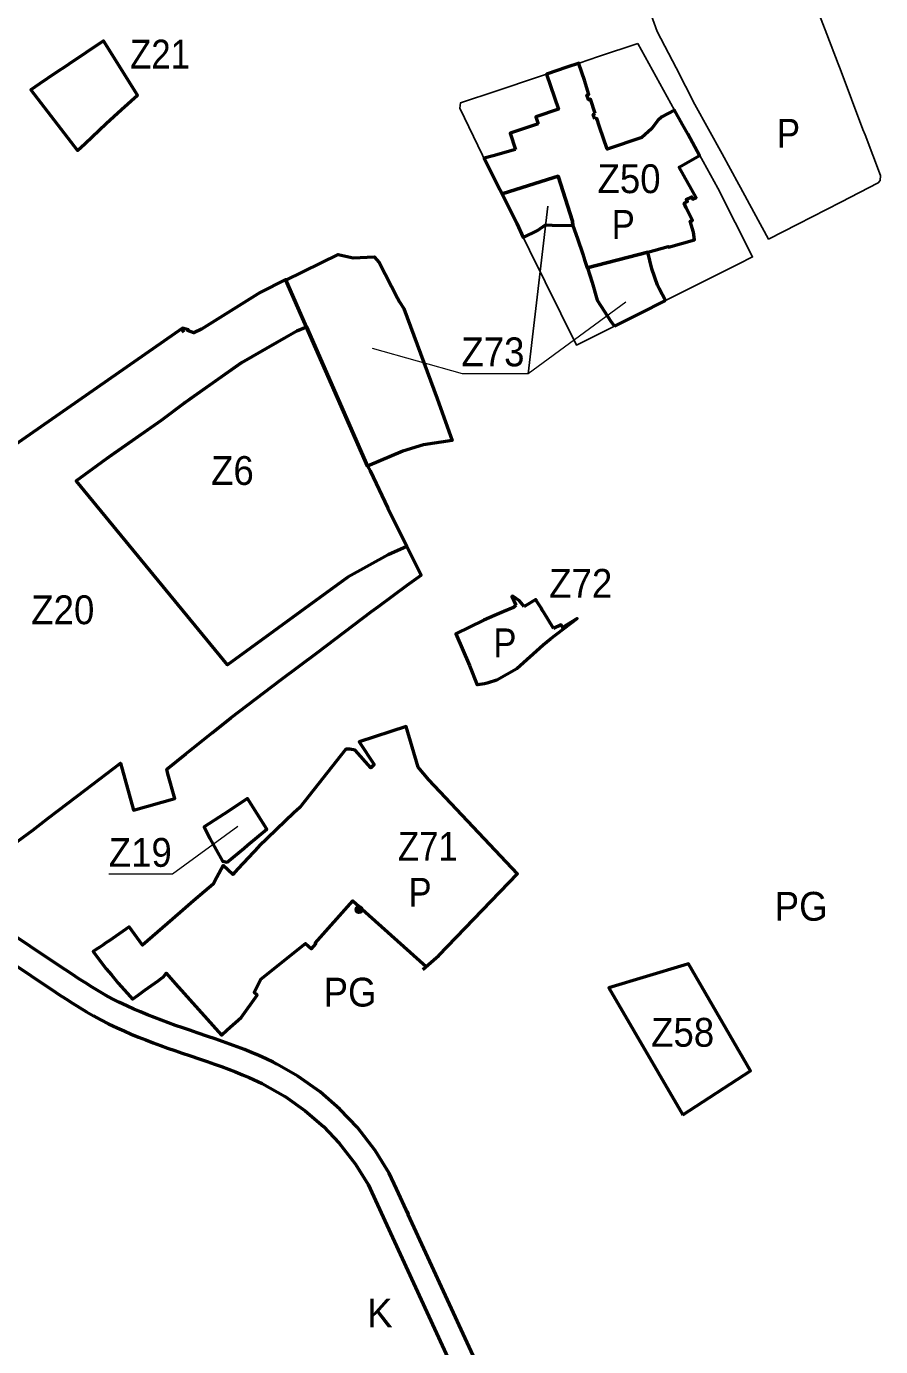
# Model space of a CAD drawing. Extents: x -650246 to -642674, y -1074280 to -1066767.
# Drawn here: x -648043 to -647332, y -1071788 to -1070690 of the extents above; entities that cross this region are included whole.
import ezdxf

# ---------------------------------------------------------------- set-up
doc = ezdxf.new("R2010")
doc.units = 0
doc.header["$LTSCALE"] = 9.6
doc.header["$PDMODE"] = 32
doc.header["$PDSIZE"] = 4.8
for name, color, linetype, lineweight in [('42', 7, 'Continuous', 25), ('44', 7, 'Continuous', 53), ('45', 7, 'Continuous', 53), ('46', 7, 'Continuous', 13), ('48', 7, 'Continuous', 13), ('60', 7, 'Continuous', 35)]:
    doc.layers.add(name, color=color, linetype=linetype, lineweight=lineweight)

msp = doc.modelspace()

# ---------------------------------------------------------------- linework, layer by layer
at = {"layer": '42'}
for points in [[(-647523.27, -1070680.11), (-647518.19, -1070693.93), (-647502.59, -1070724.13), (-647486.84, -1070754.54), (-647464.3, -1070795.6), (-647450.23, -1070821.25), (-647448.84, -1070823.79), (-647437.79, -1070844.12), (-647425.58, -1070866.7), (-647401.15, -1070854.25), (-647365.48, -1070835.85), (-647334.27, -1070819.86), (-647332.51, -1070817.97), (-647332.25, -1070813.72), (-647345.18, -1070779.89), (-647346.96, -1070775.41), (-647365.94, -1070725.08), (-647367.67, -1070720.73), (-647377.04, -1070696.22), (-647386.39, -1070671.74)], [(-647717.363, -1071306.29), (-647727.368, -1071272.362), (-647766.35, -1071285.11), (-647753.89, -1071303.94), (-647756.67, -1071306.77), (-647769.85, -1071291.91), (-647774.14, -1071291.34), (-647777.4, -1071291.32), (-647815.95, -1071339.71), (-647820.93, -1071344.25), (-647849.86, -1071372.18), (-647867.45, -1071390.95), (-647871.68, -1071395.59), (-647879.76, -1071387.96), (-647885.05, -1071397.88), (-647888.11, -1071403.61), (-647895.29, -1071409.81), (-647904.3, -1071417.58), (-647911.04, -1071423.39), (-647913.31, -1071425.35), (-647921.96, -1071432.81), (-647946.78, -1071454.23), (-647957.906, -1071439.06), (-647974.66, -1071450.62), (-647977.28, -1071452.43), (-647979.88, -1071454.22), (-647982.46, -1071456), (-647985.06, -1071457.79), (-647987.8, -1071459.68), (-647984, -1071465), (-647977.13, -1071474.05), (-647972.76, -1071479)], [(-647710.546, -1071472.023), (-647700.078, -1071462.96), (-647634.524, -1071394.901), (-647708.429, -1071316.821), (-647717.363, -1071306.29)], [(-647803.1, -1071452.66), (-647771.82, -1071417.42), (-647710.546, -1071472.023)], [(-647848.4, -1071482.78), (-647810.97, -1071452.92), (-647806.15, -1071457.48)], [(-647806.15, -1071457.48), (-647802.53, -1071453.19), (-647803.1, -1071452.66)], [(-647972.76, -1071479), (-647967.13, -1071486.01), (-647957.07, -1071497.13), (-647955.14, -1071499.23), (-647950.56, -1071495.85), (-647944.81, -1071491.78), (-647939.31, -1071487.88), (-647933.88, -1071484.04), (-647931.17, -1071482.12), (-647929.26, -1071480.77), (-647927.2, -1071477.54), (-647919.22, -1071486.5), (-647881.16, -1071529.25)], [(-647881.16, -1071529.25), (-647876.27, -1071524.96), (-647864.69, -1071514.65), (-647851.45, -1071495.96), (-647853.77, -1071493.78), (-647848.4, -1071482.78)]]:
    msp.add_lwpolyline(points, dxfattribs=at)
msp.add_lwpolyline([(-647534.33, -1070703.84), (-647567.08, -1070714.8), (-647583.22, -1070720.2), (-647651.82, -1070743.17), (-647682.08, -1070753.29), (-647682.67, -1070757.67), (-647663.71, -1070796.77), (-647585.55, -1070954.94), (-647553.94, -1070939.11), (-647532.58, -1070928.392), (-647511.37, -1070917.79), (-647501.26, -1070912.72), (-647450.8, -1070887.42), (-647438.82, -1070881.43), (-647467.89, -1070824.15), (-647480.13, -1070802.09), (-647503.76, -1070759.31)], close=True, dxfattribs=at)
at = {"layer": '44'}
for points in [[(-647834.953, -1071553.406), (-647837.929, -1071551.872), (-647843.891, -1071549), (-647849.898, -1071546.282), (-647855.937, -1071543.707), (-647861.998, -1071541.254), (-647868.073, -1071538.911), (-647874.155, -1071536.658), (-647880.233, -1071534.48), (-647886.305, -1071532.36), (-647892.363, -1071530.282), (-647901.28, -1071527.249), (-647907.294, -1071525.204), (-647913.282, -1071523.152), (-647919.238, -1071521.081), (-647925.157, -1071518.976), (-647931.035, -1071516.824), (-647936.866, -1071514.613), (-647942.644, -1071512.329), (-647948.363, -1071509.96), (-647954.016, -1071507.496), (-647959.792, -1071504.833), (-647966.547, -1071501.883), (-647972.035, -1071499.009), (-647977.67, -1071495.885), (-647983.266, -1071492.628), (-647988.829, -1071489.259), (-647994.366, -1071485.79), (-647999.887, -1071482.241), (-648005.399, -1071478.627), (-648010.917, -1071474.963), (-648016.446, -1071471.268), (-648063.593, -1071439.723)], [(-648074.86, -1071456.248), (-648027.562, -1071487.894), (-648022.005, -1071491.607), (-648016.415, -1071495.321), (-648010.777, -1071499.017), (-648005.082, -1071502.678), (-647999.319, -1071506.287), (-647993.478, -1071509.826), (-647987.55, -1071513.275), (-647981.525, -1071516.615), (-647975.201, -1071519.929), (-647967.982, -1071523.081), (-647962.2, -1071525.746), (-647956.187, -1071528.368), (-647950.146, -1071530.869), (-647944.088, -1071533.263), (-647938.019, -1071535.566), (-647931.945, -1071537.788), (-647925.874, -1071539.949), (-647919.808, -1071542.058), (-647913.756, -1071544.132), (-647907.72, -1071546.185), (-647898.827, -1071549.208), (-647892.847, -1071551.26), (-647886.903, -1071553.336), (-647881.001, -1071555.45), (-647875.147, -1071557.619), (-647869.348, -1071559.856), (-647863.611, -1071562.177), (-647857.944, -1071564.594), (-647847.103, -1071569.497)], [(-647725.629, -1071678.373), (-647735.352, -1071657.117), (-647741.34, -1071644.028), (-647753.065, -1071625.201), (-647767.784, -1071606.225), (-647782.408, -1071590.847), (-647798.911, -1071576.526), (-647817.375, -1071563.458), (-647834.953, -1071553.406)], [(-647847.103, -1071569.497), (-647828.141, -1071580.34), (-647811.272, -1071592.28), (-647796.24, -1071605.324), (-647782.97, -1071619.278)], [(-647782.97, -1071619.278), (-647769.498, -1071636.647), (-647758.994, -1071653.513), (-647743.48, -1071687.426), (-647611.514, -1071974.086)], [(-647563.77, -1071994.38), (-647564.751, -1071987.939), (-647566.62, -1071981.3), (-647569.422, -1071974.943), (-647573.283, -1071969.627), (-647575.415, -1071967.709), (-647577.881, -1071965.979), (-647581.036, -1071964.346), (-647584.363, -1071963.196), (-647588.064, -1071962.51), (-647591.518, -1071962.387), (-647594.731, -1071962.714), (-647725.614, -1071678.405), (-647726.774, -1071675.885), (-647725.629, -1071678.373)]]:
    msp.add_lwpolyline(points, dxfattribs=at)
at = {"layer": '45'}
for p, q in [((-647914.73, -1070941.682), (-647912.347, -1070944.065)), ((-647914.73, -1070941.682), (-647912.347, -1070944.065)), ((-647713.442, -1071474.53), (-647700.078, -1071462.96)), ((-647713.442, -1071474.53), (-647700.078, -1071462.96))]:
    msp.add_line(p, q, dxfattribs=at)
for points in [[(-648032.601, -1070737.472), (-648039.82, -1070742.33), (-648000.85, -1070792.88), (-647994.63, -1070787.05), (-647982.89, -1070776.05), (-647976.97, -1070770.51), (-647964.21, -1070758.77), (-647951.11, -1070746.78), (-647979.17, -1070701.65), (-648008.28, -1070720.96), (-648009.29, -1070721.79), (-648019.49, -1070728.65)], [(-647827.363, -1070900.725), (-647783.95, -1070879.58), (-647771.47, -1070882.27), (-647753.81, -1070881.3), (-647749.75, -1070886.1), (-647734.48, -1070915.94), (-647732.97, -1070918.87), (-647729.27, -1070924.35), (-647701.45, -1070999.4), (-647688.9, -1071034.18), (-647712.74, -1071037.99), (-647730.17, -1071043.21), (-647759.52, -1071055.67)], [(-647827.363, -1070900.725), (-647783.95, -1070879.58), (-647771.47, -1070882.27), (-647753.81, -1070881.3), (-647749.75, -1070886.1), (-647734.48, -1070915.94), (-647732.97, -1070918.87), (-647729.27, -1070924.35), (-647701.45, -1070999.4), (-647688.9, -1071034.18), (-647712.74, -1071037.99), (-647730.17, -1071043.21), (-647759.52, -1071055.67)], [(-648001.766, -1071068.02), (-648001.922, -1071067.83), (-647973.304, -1071046.814), (-647930.96, -1071017.383), (-647912.11, -1071003.11), (-647906.9, -1070999.39), (-647875.248, -1070977.173), (-647864.03, -1070969.3), (-647843.928, -1070957.692), (-647818.33, -1070942.91), (-647810.243, -1070939.825), (-647759.52, -1071055.67), (-647757.19, -1071059.66), (-647742.64, -1071090.72), (-647726.74, -1071122.48), (-647742.35, -1071129.43), (-647775.982, -1071148.001), (-647775.982, -1071148.001), (-647875.939, -1071221.104)], [(-647974.66, -1071450.62), (-647977.28, -1071452.43), (-647979.88, -1071454.22), (-647982.46, -1071456), (-647985.06, -1071457.79), (-647987.8, -1071459.68), (-647984, -1071465), (-647977.13, -1071474.05), (-647972.76, -1071479), (-647967.13, -1071486.01), (-647957.07, -1071497.13), (-647955.14, -1071499.23), (-647950.56, -1071495.85), (-647944.81, -1071491.78), (-647939.31, -1071487.88), (-647933.88, -1071484.04), (-647931.17, -1071482.12), (-647929.26, -1071480.77), (-647927.2, -1071477.54), (-647919.22, -1071486.5), (-647881.16, -1071529.25), (-647876.27, -1071524.96), (-647864.69, -1071514.65), (-647851.45, -1071495.96), (-647853.77, -1071493.78), (-647848.4, -1071482.78), (-647810.97, -1071452.92), (-647806.15, -1071457.48), (-647802.53, -1071453.19), (-647803.1, -1071452.66), (-647771.82, -1071417.42), (-647710.546, -1071472.023), (-647700.078, -1071462.96), (-647634.524, -1071394.901), (-647708.429, -1071316.821), (-647717.363, -1071306.29), (-647727.368, -1071272.362), (-647766.35, -1071285.11), (-647753.89, -1071303.94), (-647756.67, -1071306.77), (-647769.85, -1071291.91), (-647774.14, -1071291.34), (-647777.4, -1071291.32), (-647815.95, -1071339.71), (-647820.93, -1071344.25), (-647849.86, -1071372.18), (-647867.45, -1071390.95), (-647871.68, -1071395.59), (-647879.76, -1071387.96), (-647885.05, -1071397.88), (-647888.11, -1071403.61), (-647895.29, -1071409.81), (-647904.3, -1071417.58), (-647911.04, -1071423.39), (-647913.31, -1071425.35), (-647921.96, -1071432.81), (-647946.78, -1071454.23), (-647957.906, -1071439.06)], [(-647974.66, -1071450.62), (-647977.28, -1071452.43), (-647979.88, -1071454.22), (-647982.46, -1071456), (-647985.06, -1071457.79), (-647987.8, -1071459.68), (-647984, -1071465), (-647977.13, -1071474.05), (-647972.76, -1071479), (-647967.13, -1071486.01), (-647957.07, -1071497.13), (-647955.14, -1071499.23), (-647950.56, -1071495.85), (-647944.81, -1071491.78), (-647939.31, -1071487.88), (-647933.88, -1071484.04), (-647931.17, -1071482.12), (-647929.26, -1071480.77), (-647927.2, -1071477.54), (-647919.22, -1071486.5), (-647881.16, -1071529.25), (-647876.27, -1071524.96), (-647864.69, -1071514.65), (-647851.45, -1071495.96), (-647853.77, -1071493.78), (-647848.4, -1071482.78), (-647810.97, -1071452.92), (-647806.15, -1071457.48), (-647802.53, -1071453.19), (-647803.1, -1071452.66), (-647771.82, -1071417.42), (-647710.546, -1071472.023), (-647700.078, -1071462.96), (-647634.524, -1071394.901), (-647708.429, -1071316.821), (-647717.363, -1071306.29), (-647727.368, -1071272.362), (-647766.35, -1071285.11), (-647753.89, -1071303.94), (-647756.67, -1071306.77), (-647769.85, -1071291.91), (-647774.14, -1071291.34), (-647777.4, -1071291.32), (-647815.95, -1071339.71), (-647820.93, -1071344.25), (-647849.86, -1071372.18), (-647867.45, -1071390.95), (-647871.68, -1071395.59), (-647879.76, -1071387.96), (-647885.05, -1071397.88), (-647888.11, -1071403.61), (-647895.29, -1071409.81), (-647904.3, -1071417.58), (-647911.04, -1071423.39), (-647913.31, -1071425.35), (-647921.96, -1071432.81), (-647946.78, -1071454.23), (-647957.906, -1071439.06)], [(-647879.09, -1071345.3), (-647895.37, -1071355.96), (-647890.7, -1071365.52), (-647880.14, -1071384.32), (-647876.34, -1071385.2), (-647862.25, -1071373.55), (-647859.44, -1071371.23), (-647843.23, -1071357.82), (-647859.31, -1071332.34)], [(-647879.09, -1071345.3), (-647895.37, -1071355.96), (-647890.7, -1071365.52), (-647880.14, -1071384.32), (-647876.34, -1071385.2), (-647862.25, -1071373.55), (-647859.44, -1071371.23), (-647843.23, -1071357.82), (-647859.31, -1071332.34)], [(-647497.04, -1071595.66), (-647440.67, -1071558.93), (-647492.3, -1071470), (-647495.85, -1071471.06), (-647558.654, -1071489.738)], [(-647497.04, -1071595.66), (-647440.67, -1071558.93), (-647492.3, -1071470), (-647495.85, -1071471.06), (-647558.654, -1071489.738)]]:
    msp.add_lwpolyline(points, close=True, dxfattribs=at)
for points in [[(-647569.92, -1070762.24), (-647573.88, -1070750.25), (-647575.58, -1070750.83), (-647576.81, -1070746.86), (-647575.09, -1070746.33), (-647578.79, -1070734.33), (-647583.38, -1070720.9), (-647583.22, -1070720.2), (-647593.6, -1070723.68), (-647610.33, -1070729.28), (-647600.53, -1070758.65), (-647619.2, -1070764.85), (-647617.36, -1070770.69)], [(-647636.12, -1070792.13), (-647654.89, -1070797.23), (-647662.26, -1070799.23), (-647650.908, -1070822.34), (-647647.405, -1070829.08), (-647609.58, -1070817.06), (-647600.8, -1070814.27), (-647588.89, -1070851.67), (-647588.4, -1070855.25), (-647584.6, -1070866.3), (-647580.22, -1070879.3), (-647578.703, -1070883.851), (-647578.703, -1070883.851), (-647576.469, -1070890.564), (-647526.13, -1070877.41), (-647509.1, -1070872.96), (-647508.96, -1070873.41), (-647487.16, -1070867.32), (-647487.91, -1070860.91), (-647490.92, -1070851.82), (-647488.8, -1070851.12), (-647494.1, -1070840.58), (-647495.93, -1070836.86), (-647493.16, -1070835.5), (-647494.03, -1070833.64), (-647489.55, -1070831.53), (-647488.75, -1070833.37), (-647485.9, -1070832), (-647500.07, -1070806.87), (-647500.07, -1070806.87), (-647483.16, -1070797.07), (-647492.81, -1070779.18), (-647492.81, -1070779.18), (-647497.227, -1070771.165), (-647503.76, -1070759.31), (-647514.49, -1070764.93), (-647517.61, -1070767.89), (-647523.07, -1070774.86), (-647531.05, -1070782.23), (-647560.06, -1070791.72), (-647566.26, -1070773.148)], [(-647570.27, -1070766.86), (-647571.63, -1070762.82), (-647569.92, -1070762.24)], [(-647617.36, -1070770.69), (-647619.12, -1070771.28), (-647640.66, -1070778.47), (-647636.12, -1070792.13)], [(-647566.26, -1070773.148), (-647568.55, -1070766.29), (-647570.27, -1070766.86)], [(-647588.4, -1070855.25), (-647588.89, -1070851.67), (-647600.8, -1070814.27), (-647609.58, -1070817.06), (-647647.405, -1070829.08)], [(-647588.4, -1070855.25), (-647588.89, -1070851.67), (-647600.8, -1070814.27), (-647609.58, -1070817.06), (-647647.405, -1070829.08)], [(-647647.405, -1070829.08), (-647635.11, -1070853.786), (-647629.92, -1070865.35), (-647618.01, -1070859.42), (-647611.3, -1070854.9), (-647605.64, -1070854.99), (-647588.4, -1070855.25)], [(-647647.405, -1070829.08), (-647635.11, -1070853.786), (-647629.92, -1070865.35), (-647618.01, -1070859.42), (-647611.3, -1070854.9), (-647605.64, -1070854.99), (-647588.4, -1070855.25)], [(-647511.37, -1070917.79), (-647516.66, -1070907.8), (-647518.12, -1070905.05), (-647522.74, -1070891.48), (-647526.13, -1070877.41), (-647576.469, -1070890.564)], [(-647576.469, -1070890.564), (-647576.43, -1070890.68), (-647572.32, -1070902.72), (-647568.2, -1070917.54), (-647556.52, -1070935.59), (-647553.94, -1070939.11)], [(-648060.01, -1071374.69), (-648038.18, -1071358.51), (-648025.39, -1071348.76), (-648009.31, -1071336.48), (-647994.31, -1071325.03), (-647965.26, -1071302.86), (-647954.38, -1071342), (-647919.88, -1071332.23), (-647925.6, -1071311.69), (-647926.69, -1071307.81), (-647910.73, -1071295.08), (-647907.92, -1071292.84), (-647888.77, -1071277.56), (-647873.25, -1071265.17), (-647831.565, -1071233.455), (-647801.178, -1071210.742), (-647756.03, -1071176.76), (-647750.34, -1071172.5), (-647726.56, -1071154.68), (-647714.71, -1071146.51), (-647714.71, -1071146.51), (-647719.73, -1071136.48), (-647726.74, -1071122.48), (-647742.35, -1071129.43), (-647775.982, -1071148.001), (-647808.402, -1071171.711), (-647848.51, -1071201.045), (-647875.939, -1071221.104), (-648001.766, -1071068.02), (-648001.922, -1071067.83), (-647977.41, -1071049.74), (-647930.96, -1071017.383), (-647911.838, -1071002.919), (-647912.11, -1071003.11), (-647864.29, -1070969.503), (-647838.842, -1070954.778), (-647818.33, -1070942.91), (-647810.243, -1070939.825), (-647827.527, -1070900.351), (-647848.89, -1070911.21), (-647897.76, -1070941.62), (-647904.13, -1070944.78), (-647909.42, -1070942.63), (-647908.63, -1070942.1), (-647913.45, -1070940.79), (-648062.53, -1071044.59)], [(-647553.94, -1070939.11), (-647553.94, -1070939.11), (-647550.59, -1070937.45), (-647533.31, -1070928.79), (-647511.37, -1070917.79)], [(-647629.09, -1071172.4), (-647632.93, -1071167.71), (-647638.46, -1071163.89), (-647639.32, -1071164.22), (-647635.93, -1071171.22)], [(-647629.09, -1071172.4), (-647632.93, -1071167.71), (-647638.46, -1071163.89), (-647639.32, -1071164.22), (-647635.93, -1071171.22)], [(-647612.695, -1071177.542), (-647613.91, -1071175.57), (-647614.732, -1071174.222), (-647618.446, -1071168.166), (-647618.469, -1071168.129), (-647618.77, -1071167.64), (-647619.264, -1071166.832), (-647619.34, -1071166.709), (-647628.39, -1071172.05), (-647629.09, -1071172.4)], [(-647612.695, -1071177.542), (-647613.91, -1071175.57), (-647614.732, -1071174.222), (-647618.446, -1071168.166), (-647618.469, -1071168.129), (-647618.77, -1071167.64), (-647619.264, -1071166.832), (-647619.34, -1071166.709), (-647628.39, -1071172.05), (-647629.09, -1071172.4)], [(-647635.93, -1071171.22), (-647637.87, -1071173.29), (-647646.09, -1071176.68), (-647653.85, -1071179.87), (-647662.634, -1071183.968)], [(-647635.93, -1071171.22), (-647637.87, -1071173.29), (-647646.09, -1071176.68), (-647653.85, -1071179.87), (-647662.634, -1071183.968)], [(-647604.576, -1071190.781), (-647604.888, -1071190.272), (-647612.695, -1071177.542)], [(-647604.576, -1071190.781), (-647604.888, -1071190.272), (-647612.695, -1071177.542)], [(-647662.634, -1071183.968), (-647686.01, -1071195.35), (-647686.01, -1071195.35)], [(-647662.634, -1071183.968), (-647686.01, -1071195.35), (-647686.01, -1071195.35)], [(-647674.6, -1071221.71), (-647668.226, -1071237.571), (-647667.77, -1071237.5), (-647661.99, -1071236.62), (-647658.78, -1071235.63), (-647651.93, -1071233.57), (-647635.17, -1071224.18), (-647613.09, -1071204.33), (-647607.02, -1071199.34), (-647584.92, -1071182.54), (-647597.164, -1071189.857), (-647598.215, -1071187.608), (-647604.576, -1071190.781)], [(-647674.6, -1071221.71), (-647668.226, -1071237.571), (-647667.77, -1071237.5), (-647661.99, -1071236.62), (-647658.78, -1071235.63), (-647651.93, -1071233.57), (-647635.17, -1071224.18), (-647613.09, -1071204.33), (-647607.02, -1071199.34), (-647584.92, -1071182.54), (-647597.164, -1071189.857), (-647598.215, -1071187.608), (-647604.576, -1071190.781)], [(-647686.01, -1071195.35), (-647686.01, -1071195.35), (-647674.6, -1071221.71)], [(-647686.01, -1071195.35), (-647686.01, -1071195.35), (-647674.6, -1071221.71)]]:
    msp.add_lwpolyline(points, dxfattribs=at)
msp.add_point((-647766.557, -1071424.793), dxfattribs=at)
at = {"layer": '46'}
for points in [[(-647544.337, -1070919.163), (-647625.809, -1070978.773), (-647609.46, -1070839.305), (-647625.809, -1070978.773), (-647680.348, -1070978.773), (-647755.299, -1070957.715)], [(-647544.337, -1070919.163), (-647625.809, -1070978.773), (-647609.46, -1070839.305), (-647625.809, -1070978.773), (-647680.348, -1070978.773), (-647755.299, -1070957.715)], [(-647974.97, -1071395.111), (-647921.786, -1071395.111), (-647867.57, -1071355.322)], [(-647974.97, -1071395.111), (-647921.786, -1071395.111), (-647867.57, -1071355.322)]]:
    msp.add_lwpolyline(points, dxfattribs=at)

# ---------------------------------------------------------------- texts
for s, width, p in [('Z21', 0.9, (-647957.11, -1070724.677)), ('Z50', 0.95, (-647567.967, -1070828.405)), ('Z50', 0.95, (-647567.967, -1070828.405)), ('Z73', 0.95, (-647681.324, -1070972.53)), ('Z73', 0.95, (-647681.324, -1070972.53)), ('Z6', 0.95, (-647889.738, -1071071.271)), ('Z72', 0.95, (-647608.212, -1071165.192)), ('Z72', 0.95, (-647608.212, -1071165.192)), ('Z20', 0.95, (-648039.444, -1071187.201)), ('Z19', 0.95, (-647974.958, -1071389.14)), ('Z19', 0.95, (-647974.958, -1071389.14)), ('Z71', 0.9, (-647734.152, -1071384.125)), ('Z71', 0.9, (-647734.152, -1071384.125)), ('Z58', 0.95, (-647523.363, -1071538.888)), ('Z58', 0.95, (-647523.363, -1071538.888))]:
    msp.add_text(s, height=24, dxfattribs=dict(at, width=width)).set_placement(p)
at = {"layer": '48'}
msp.add_text('K', height=24, dxfattribs=at).set_placement((-647759.879, -1071772.452))
msp.add_text('K', height=24, dxfattribs=at).set_placement((-647759.879, -1071772.452))
at = {"layer": '60'}
for s, width, p in [('P', 0.9, (-647418.572, -1070790.564)), ('P', 0.9, (-647418.572, -1070790.564)), ('P', 0.9, (-647556.162, -1070866.47)), ('P', 0.9, (-647556.162, -1070866.47)), ('P', 0.9, (-647654.706, -1071214.743)), ('P', 0.9, (-647654.706, -1071214.743)), ('P', 0.9, (-647725.36, -1071422.368)), ('P', 0.9, (-647725.36, -1071422.368)), ('PG', 0.95, (-647420.449, -1071434.013)), ('PG', 0.95, (-647420.449, -1071434.013)), ('PG', 0.95, (-647796.031, -1071505.454)), ('PG', 0.95, (-647796.031, -1071505.454))]:
    msp.add_text(s, height=24, dxfattribs=dict(at, width=width)).set_placement(p)

doc.saveas('drawing.dxf')
